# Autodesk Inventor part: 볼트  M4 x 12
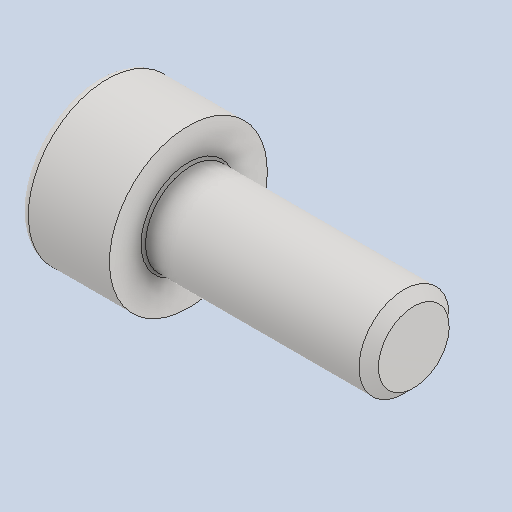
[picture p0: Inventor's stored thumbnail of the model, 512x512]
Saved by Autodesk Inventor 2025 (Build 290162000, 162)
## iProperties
Created: 2025-08
Part Number: 볼트  M4 x 12
Material: 스테인리스강
Description: 6각머리 태핑 나사
Document SubType Name: Modeling
Designer: infra02
Density: 8.08 g/cm^3
Appearance: 기본값
Author: jhkim
Sending System: Autodesk Inventor 2026
Preprocessor: ST-DEVELOPER v20.1
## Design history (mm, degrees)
feature "Solid1"
node "솔리드1"
